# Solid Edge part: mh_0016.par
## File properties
Title: grip_r_f
Author: edge
Template: normal.par
Last saved by: edge
Revision: 30
Application: Solid Edge
Material: ABS
非切断部品: False
文書内容のタイプ: 0
Density: 0.001200 g/mm^3
Accuracy: 0.99
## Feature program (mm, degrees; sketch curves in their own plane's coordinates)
sketch for "unnamed Protrusion 1" plane through (0, 0, 0) normal (0, 0, 1) x-axis (1, 0, 0)
  line (-50, 0) -> (0, 0)
  line (0, 0) -> (0, -80)
  line (0, -80) -> (-50, -80)
  line (-50, -80) -> (-50, 0)
extrude "unnamed Protrusion 1" add finite 15 along -normal
thinwall "Thinwall_1"  Thickness = 1 mm
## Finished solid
Body 1: solid body, 11 faces, 24 edges, 16 vertices.
  Faces by surface: plane 11
  Edges by curve: line 24
Bounding box of the edges (mm): 50.000 x 80.000 x 15.000, from (-50, -80, -15) to (0, 0, 0).
Planar faces by outward normal: +x 2, +y 2, +z 2, -x 2, -y 2, -z 1
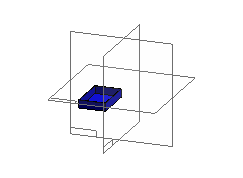
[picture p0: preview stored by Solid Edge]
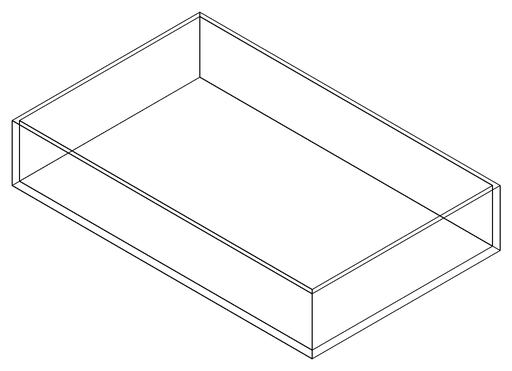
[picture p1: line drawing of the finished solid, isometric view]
